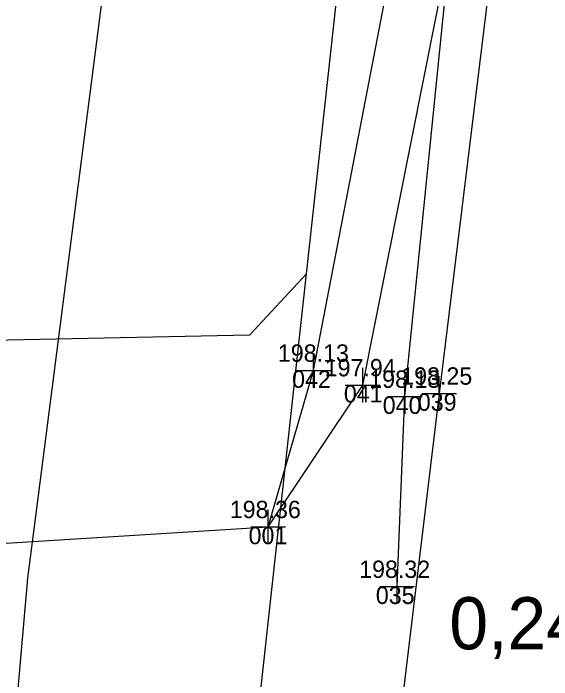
# Model space of a CAD drawing. Extents: x -706655 to -706193, y -1036183 to -1035040.
# Drawn here: x -706624.14 to -706608.64, y -1035107.9 to -1035088.72 of the extents above; entities that cross this region are included whole.
import ezdxf

# ---------------------------------------------------------------- set-up
doc = ezdxf.new("R2010")
doc.units = 0
for name, color, linetype in [('CETIN', 7, 'Continuous'), ('Hranice parcel', 7, 'Continuous'), ('křížky', 7, 'Continuous'), ('Nová vrstva (0)', 7, 'Continuous'), ('Stávající terén', 7, 'Continuous'), ('výšky', 7, 'Continuous'), ('čísla bodu', 7, 'Continuous')]:
    doc.layers.add(name, color=color, linetype=linetype)

msp = doc.modelspace()

# ---------------------------------------------------------------- linework, layer by layer
at = {"layer": 'CETIN'}
msp.add_lwpolyline([(-706632.29, -1035178.176), (-706624.38, -1035112.55), (-706623.72, -1035104.98), (-706623.414, -1035102.598), (-706615.872, -1035043.919)], dxfattribs=at)
at = {"layer": 'Hranice parcel'}
for p, q in [((-706615.7, -1035096.22), (-706610.89, -1035052.274)), ((-706617.66, -1035114.1), (-706615.7, -1035096.22))]:
    msp.add_line(p, q, dxfattribs=at)
msp.add_lwpolyline([(-706615.7, -1035096.22), (-706617.34, -1035097.98), (-706634.51, -1035098.34), (-706644.76, -1035099.32), (-706645.624, -1035099.305)], dxfattribs=at)
at = {"layer": 'křížky'}
for p, q in [((-706615.5, -1035099.5), (-706615.5, -1035098.5)), ((-706614.08, -1035099.92), (-706614.08, -1035098.92)), ((-706616, -1035099), (-706615, -1035099)), ((-706615.5, -1035099), (-706615.5, -1035099)), ((-706612.87, -1035100.25), (-706612.87, -1035099.25)), ((-706611.88, -1035100.16), (-706611.88, -1035099.16)), ((-706614.58, -1035099.42), (-706613.58, -1035099.42)), ((-706614.08, -1035099.42), (-706614.08, -1035099.42)), ((-706612.38, -1035099.66), (-706611.38, -1035099.66)), ((-706611.88, -1035099.66), (-706611.88, -1035099.66)), ((-706613.37, -1035099.75), (-706612.37, -1035099.75)), ((-706612.87, -1035099.75), (-706612.87, -1035099.75)), ((-706616.8, -1035104), (-706616.8, -1035103)), ((-706617.3, -1035103.5), (-706616.3, -1035103.5)), ((-706616.8, -1035103.5), (-706616.8, -1035103.5)), ((-706613.09, -1035105.72), (-706613.09, -1035104.72)), ((-706613.59, -1035105.22), (-706612.59, -1035105.22)), ((-706613.09, -1035105.22), (-706613.09, -1035105.22))]:
    msp.add_line(p, q, dxfattribs=at)
at = {"layer": 'Stávající terén'}
for points in [[(-706616.8, -1035103.5), (-706615.5, -1035099), (-706613.16, -1035086.84), (-706611.9, -1035074.82)], [(-706629.59, -1035104.3), (-706616.8, -1035103.5), (-706614.08, -1035099.42), (-706611.61, -1035087.02), (-706610.92, -1035075.19)], [(-706608.917, -1035075.29), (-706610.31, -1035086.81), (-706611.88, -1035099.66), (-706615.39, -1035128.84), (-706617.25, -1035146.23)], [(-706613.09, -1035105.22), (-706612.87, -1035099.75), (-706611.58, -1035087.02), (-706609.77, -1035075.25)]]:
    msp.add_lwpolyline(points, dxfattribs=at)
at = {"layer": 'čísla bodu'}
for p, q in [((-706615.5, -1035099.5), (-706615.5, -1035098.5)), ((-706614.08, -1035099.92), (-706614.08, -1035098.92)), ((-706616, -1035099), (-706615, -1035099)), ((-706615.5, -1035099), (-706615.5, -1035099)), ((-706612.87, -1035100.25), (-706612.87, -1035099.25)), ((-706611.88, -1035100.16), (-706611.88, -1035099.16)), ((-706614.58, -1035099.42), (-706613.58, -1035099.42)), ((-706614.08, -1035099.42), (-706614.08, -1035099.42)), ((-706612.38, -1035099.66), (-706611.38, -1035099.66)), ((-706611.88, -1035099.66), (-706611.88, -1035099.66)), ((-706613.37, -1035099.75), (-706612.37, -1035099.75)), ((-706612.87, -1035099.75), (-706612.87, -1035099.75)), ((-706616.8, -1035104), (-706616.8, -1035103)), ((-706617.3, -1035103.5), (-706616.3, -1035103.5)), ((-706616.8, -1035103.5), (-706616.8, -1035103.5)), ((-706613.09, -1035105.72), (-706613.09, -1035104.72)), ((-706613.59, -1035105.22), (-706612.59, -1035105.22)), ((-706613.09, -1035105.22), (-706613.09, -1035105.22))]:
    msp.add_line(p, q, dxfattribs=at)

# ---------------------------------------------------------------- texts
at = {"layer": 'Nová vrstva (0)'}
msp.add_text('0,242', height=1.5, dxfattribs=at).set_placement((-706611.587, -1035107.024))
at = {"layer": 'výšky'}
for s, p in [('198.13', (-706616.522, -1035098.75)), ('197.94', (-706615.174, -1035099.17)), ('198.25', (-706612.972, -1035099.41)), ('198.13', (-706613.892, -1035099.5)), ('198.36', (-706617.906, -1035103.25)), ('198.32', (-706614.182, -1035104.97))]:
    msp.add_text(s, height=0.5, dxfattribs=at).set_placement(p)
at = {"layer": 'čísla bodu'}
for s, p in [('042', (-706616.112, -1035099.5)), ('041', (-706614.622, -1035099.92)), ('039', (-706612.494, -1035100.16)), ('040', (-706613.504, -1035100.25)), ('001', (-706617.364, -1035104)), ('035', (-706613.702, -1035105.72))]:
    msp.add_text(s, height=0.5, dxfattribs=at).set_placement(p)

doc.saveas('drawing.dxf')
